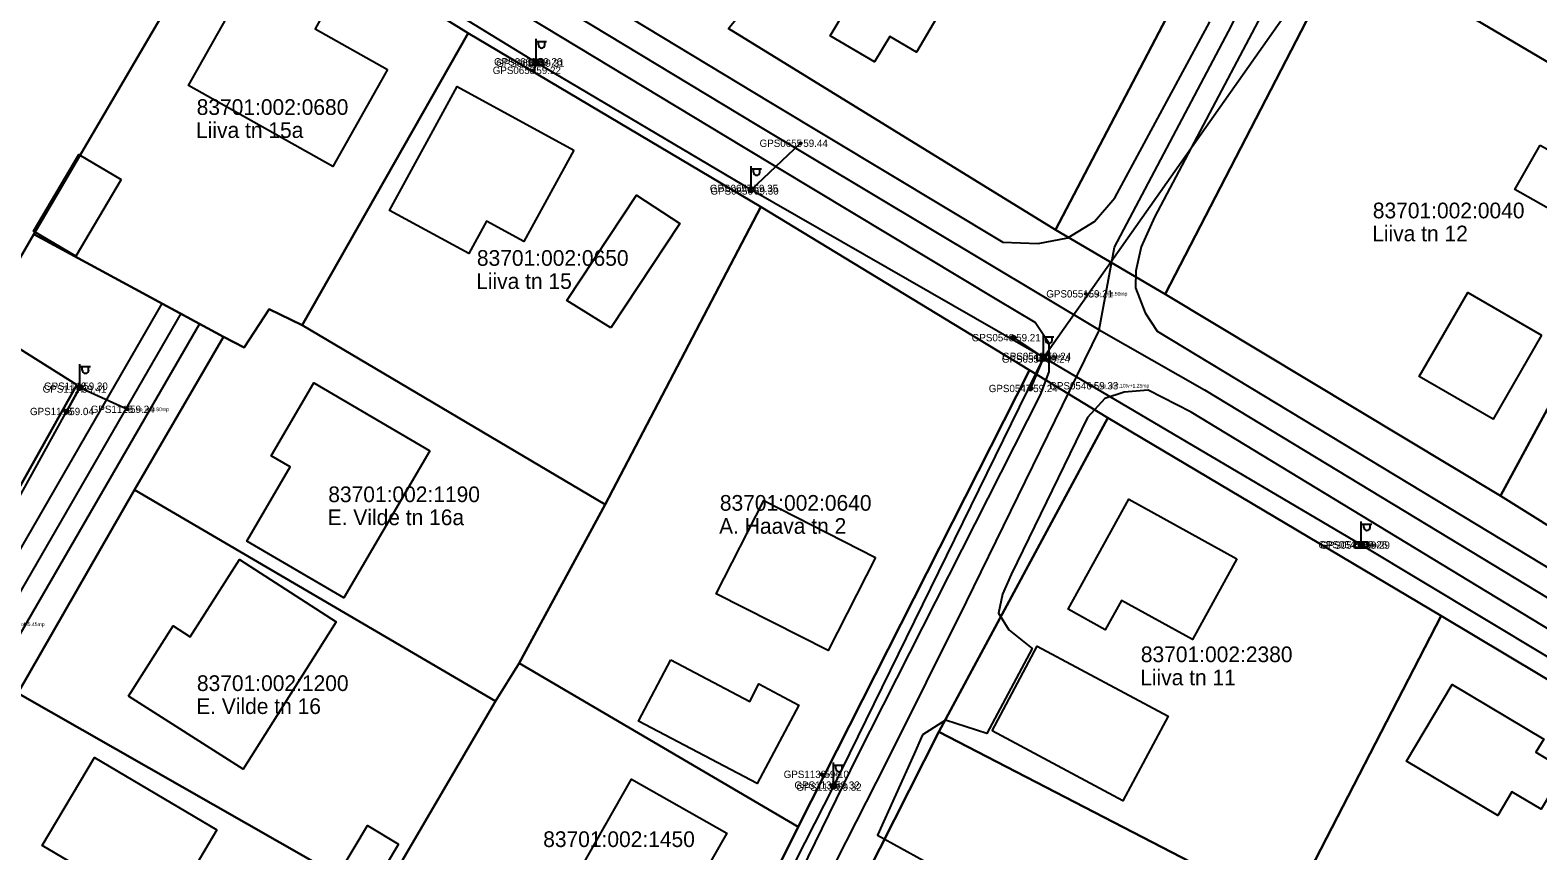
# Model space of a CAD drawing. Extents: x 580119 to 583377, y 6518915 to 6520820.
# Drawn here: x 581802.2 to 581946.3, y 6520148.1 to 6520226.6 of the extents above; entities that cross this region are included whole.
import ezdxf

# ---------------------------------------------------------------- set-up
doc = ezdxf.new("R2010")
doc.units = 0
for name, color, linetype in [('ELRAJATISMP', 7, 'Continuous'), ('Hoone Elu- või ühiskondlik hoone', 7, 'Continuous'), ('Hoone Kõrval- või tootmishoone', 7, 'Continuous'), ('L_AADRESS', 7, 'Continuous'), ('MAAMUDEL', 7, 'Continuous'), ('MOOTKORG-EH2000', 7, 'Continuous'), ('MOOTMPUNKT', 7, 'Continuous'), ('MOOTNR', 7, 'Continuous'), ('MPOHULIIN', 7, 'Continuous'), ('PIIR', 7, 'Continuous'), ('POST', 7, 'Continuous'), ('Rippe kõrgus', 7, 'Continuous'), ('Tee Liiklusala', 7, 'Continuous'), ('Tee Tänav Püsikate', 7, 'Continuous'), ('TUNNUS', 7, 'Continuous')]:
    doc.layers.add(name, color=color, linetype=linetype)

msp = doc.modelspace()

# ---------------------------------------------------------------- linework, layer by layer
at = {"layer": 'ELRAJATISMP'}
for p, q in [((581850.41, 6520223.81), (581850.41, 6520223.22)), ((581850.69, 6520223.81), (581850.69, 6520223.22)), ((581898.91, 6520195.58), (581898.91, 6520194.99)), ((581899.19, 6520195.58), (581899.19, 6520194.99)), ((581929.32, 6520177.68), (581929.32, 6520177.08)), ((581929.59, 6520177.68), (581929.59, 6520177.08))]:
    msp.add_line(p, q, dxfattribs=at)
for points in [[(581849.95, 6520223.81), (581851.15, 6520223.81), (581851.15, 6520223.22), (581849.95, 6520223.22)], [(581898.45, 6520195.58), (581899.65, 6520195.58), (581899.65, 6520194.99), (581898.45, 6520194.99)], [(581928.86, 6520177.68), (581930.05, 6520177.68), (581930.05, 6520177.08), (581928.86, 6520177.08)]]:
    msp.add_lwpolyline(points, close=True, dxfattribs=at)
at = {"layer": 'Hoone Elu- või ühiskondlik hoone'}
for points in [[(581891.94, 6520233.04), (581886.91, 6520224.51), (581884.36, 6520226.01), (581882.91, 6520223.56), (581878.68, 6520226.06), (581880.13, 6520228.52), (581877.03, 6520230.34), (581882.05, 6520238.87)], [(581836.34, 6520222.85), (581831.12, 6520213.56), (581817.32, 6520221.3), (581823.33, 6520232.01), (581830.22, 6520228.15), (581829.43, 6520226.73)], [(581854.16, 6520215.14), (581849.38, 6520206.38), (581845.8, 6520208.34), (581844.11, 6520205.25), (581836.55, 6520209.37), (581843.02, 6520221.22)], [(581946.68, 6520197.44), (581942.07, 6520189.42), (581934.99, 6520193.49), (581939.62, 6520201.52)], [(581840.4, 6520186.38), (581832.16, 6520172.31), (581822.89, 6520177.74), (581827.04, 6520184.84), (581825.21, 6520185.91), (581829.29, 6520192.88)], [(581883.01, 6520176.19), (581878.46, 6520167.27), (581867.77, 6520172.71), (581872.32, 6520181.64)], [(581917.55, 6520176.04), (581913.31, 6520168.34), (581906.53, 6520172.08), (581904.97, 6520169.27), (581901.42, 6520171.22), (581907.22, 6520181.75)], [(581811.59, 6520162.92), (581815.85, 6520169.63), (581817.48, 6520168.59), (581822.18, 6520175.99), (581831.45, 6520170.01), (581822.54, 6520155.95)], [(581948.92, 6520155.91), (581946.66, 6520152.11), (581943.85, 6520153.78), (581942.5, 6520151.5), (581933.76, 6520156.7), (581938.12, 6520164.04), (581946.9, 6520158.82), (581946.15, 6520157.56)], [(581820.03, 6520150.12), (581815.05, 6520141.71), (581803.34, 6520148.65), (581808.33, 6520157.06)], [(581852.13, 6520141.69), (581859.68, 6520154.99), (581868.78, 6520149.82), (581865.61, 6520144.24), (581867.15, 6520143.37), (581862.77, 6520135.65)]]:
    msp.add_lwpolyline(points, close=True, dxfattribs=at)
at = {"layer": 'Hoone Kõrval- või tootmishoone'}
for points in [[(581810.89, 6520212.33), (581806.56, 6520204.98), (581802.5, 6520207.37), (581806.84, 6520214.71)], [(581946.54, 6520215.6), (581950.38, 6520213.43), (581951.22, 6520214.89), (581955.32, 6520212.57), (581952.08, 6520206.86), (581944.14, 6520211.36)], [(581857.7, 6520198.14), (581853.48, 6520200.75), (581860.14, 6520210.83), (581864.28, 6520208.1)], [(581894.14, 6520159.59), (581898.47, 6520167.69), (581910.99, 6520161.01), (581906.66, 6520152.9)], [(581863.44, 6520166.4), (581870.99, 6520162.42), (581871.86, 6520164.08), (581875.67, 6520162.07), (581871.7, 6520154.55), (581860.35, 6520160.54)], [(581837.4, 6520148.76), (581834.75, 6520144.33), (581831.78, 6520146.12), (581834.43, 6520150.54)]]:
    msp.add_lwpolyline(points, close=True, dxfattribs=at)
at = {"layer": 'MOOTMPUNKT'}
for centre in [(581850.45, 6520223.58), (581850.65, 6520223.45), (581850.32, 6520222.76), (581875.84, 6520215.79), (581871.08, 6520211.47), (581871.14, 6520211.23), (581903.11, 6520201.39), (581896.19, 6520197.2), (581899, 6520195.16), (581899.1, 6520195.41), (581806.87, 6520192.29), (581807, 6520192.56), (581897.82, 6520192.34), (581903.61, 6520192.6), (581805.66, 6520190.14), (581811.47, 6520190.35), (581929.33, 6520177.4), (581929.58, 6520177.36), (581877.86, 6520155.44), (581878.89, 6520154.41), (581879.07, 6520154.22)]:
    msp.add_circle(centre, 0.1, dxfattribs=at)
at = {"layer": 'MPOHULIIN'}
for p, q in [((581899.05, 6520195.29), (581927.38, 6520235.48)), ((581850.55, 6520223.51), (581850.32, 6520222.76)), ((581871.11, 6520211.35), (581875.84, 6520215.79))]:
    msp.add_line(p, q, dxfattribs=at)
for points in [[(582074.17, 6520090.2), (582035.13, 6520113.98), (581994.07, 6520138.74), (581958.9, 6520159.67), (581929.45, 6520177.38), (581899.05, 6520195.29), (581871.11, 6520211.35), (581850.55, 6520223.51), (581830.36, 6520235.9)], [(581761.9, 6520219.5), (581748, 6520195.87), (581734.01, 6520171.83), (581727.44, 6520138.41), (581764.38, 6520118.14), (581785.49, 6520154.65), (581795.71, 6520172.16), (581806.94, 6520192.43), (581811.47, 6520190.35)], [(581899.05, 6520195.29), (581878.98, 6520154.31), (581864.42, 6520125.7), (581863.29, 6520125.92)]]:
    msp.add_lwpolyline(points, dxfattribs=at)
at = {"layer": 'PIIR'}
for points in [[(581910.68, 6520201.36), (581900.21, 6520207.51), (581917.83, 6520241.2), (581929.38, 6520263.33), (581942.22, 6520287.85), (581953.73, 6520280.26), (581951.99, 6520279.75), (581939.33, 6520256.33), (581928.04, 6520234.91)], [(581893.75, 6520257.55), (581898.1, 6520255.28), (581897.13, 6520253.13), (581917.83, 6520241.2), (581900.21, 6520207.51), (581868.94, 6520226.76)], [(581939.33, 6520256.33), (581965.72, 6520242.24), (581963.58, 6520238.14), (581954.1, 6520219.54), (581928.04, 6520234.91)], [(581796.29, 6520255.75), (581821.83, 6520240.08), (581802.53, 6520207.1), (581797.51, 6520198.44), (581771.2, 6520213.92)], [(581821.83, 6520240.08), (581844.07, 6520226.32), (581828.18, 6520198.39), (581825.04, 6520199.93), (581822.65, 6520196.25), (581820.67, 6520197.28), (581802.53, 6520207.1)], [(581928.04, 6520234.91), (581954.1, 6520219.54), (581960.82, 6520215.52), (581942.75, 6520182.07), (581910.68, 6520201.36)], [(581844.07, 6520226.32), (581872.03, 6520209.71), (581857.14, 6520181.23), (581828.18, 6520198.39)], [(581960.82, 6520215.52), (581976.76, 6520205.4), (581992.7, 6520196.04), (581974.77, 6520162.07), (581942.75, 6520182.07)], [(581771.2, 6520213.92), (581797.51, 6520198.44), (581806.64, 6520192.68), (581792.37, 6520167.22), (581755.98, 6520188.75)], [(581857.14, 6520181.23), (581872.03, 6520209.71), (581897.71, 6520194.09), (581875.62, 6520150.43), (581848.92, 6520166.07)], [(581764.96, 6520102.57), (581721.29, 6520129.05), (581728.54, 6520142.46), (581730.99, 6520136.24), (581759.52, 6520120.17), (581766.93, 6520122.61), (581782.15, 6520149.87), (581792.37, 6520167.22), (581806.64, 6520192.68), (581797.51, 6520198.44), (581802.53, 6520207.1), (581820.67, 6520197.28), (581812.15, 6520182.64), (581800.99, 6520163.2), (581790.11, 6520144.42), (581779.28, 6520127.73), (581769.84, 6520111.32), (581765.39, 6520103.31)], [(581820.67, 6520197.28), (581822.65, 6520196.25), (581825.04, 6520199.93), (581828.18, 6520198.39), (581857.14, 6520181.23), (581848.92, 6520166.07), (581846.68, 6520162.43), (581812.15, 6520182.64)], [(581818.25, 6520012.64), (581808.31, 6520018.92), (581824.83, 6520050.4), (581836.47, 6520072.82), (581851.4, 6520101.52), (581829.9, 6520114.5), (581832.4, 6520118.89), (581853.07, 6520105.93), (581865.62, 6520130.32), (581875.62, 6520150.43), (581897.71, 6520194.09), (581905.22, 6520189.53), (581889.06, 6520159.5), (581879.18, 6520139.97), (581876.38, 6520134.67), (581873.75, 6520129.28), (581870.97, 6520123.99), (581868.38, 6520118.69), (581865.54, 6520113.3), (581862.86, 6520107.92), (581858.03, 6520098.95), (581858.58, 6520096.63), (581855.23, 6520085.11)], [(581905.22, 6520189.53), (581937.09, 6520170.6), (581922.47, 6520142.22), (581889.06, 6520159.5)], [(581812.15, 6520182.64), (581846.68, 6520162.43), (581837.68, 6520147.06), (581835.4, 6520143.6), (581800.99, 6520163.2)], [(581917.89, 6520132.56), (581922.47, 6520142.22), (581937.09, 6520170.6), (581968.64, 6520151.74), (581949.67, 6520115.03), (581931.46, 6520124.92)], [(581846.68, 6520162.43), (581848.92, 6520166.07), (581875.62, 6520150.43), (581865.62, 6520130.32), (581837.68, 6520147.06)], [(581790.11, 6520144.42), (581800.99, 6520163.2), (581835.4, 6520143.6), (581823.73, 6520125.03), (581804.32, 6520136.18), (581798.27, 6520139.74)], [(581889.06, 6520159.5), (581922.47, 6520142.22), (581917.89, 6520132.56), (581931.46, 6520124.92), (581926.36, 6520115.88), (581899.93, 6520129.4), (581889.34, 6520134.93), (581879.18, 6520139.97)]]:
    msp.add_lwpolyline(points, close=True, dxfattribs=at)
for points in [[(581968.64, 6520151.74), (581937.09, 6520170.6), (581905.22, 6520189.53), (581897.71, 6520194.09), (581872.03, 6520209.71), (581844.07, 6520226.32), (581821.83, 6520240.08)], [(581868.94, 6520226.76), (581900.21, 6520207.51), (581910.68, 6520201.36), (581942.75, 6520182.07), (581974.77, 6520162.07)]]:
    msp.add_lwpolyline(points, dxfattribs=at)
at = {"layer": 'POST'}
for p, q in [((581850.55, 6520223.76), (581850.55, 6520225.76)), ((581850.55, 6520225.51), (581851.55, 6520225.51)), ((581850.78, 6520225.19), (581850.78, 6520225.51)), ((581851.39, 6520225.19), (581851.39, 6520225.51)), ((581850.55, 6520223.51), (581850.55, 6520223.51)), ((581871.11, 6520211.6), (581871.11, 6520213.6)), ((581871.11, 6520213.35), (581872.11, 6520213.35)), ((581871.33, 6520213.03), (581871.33, 6520213.35)), ((581871.95, 6520213.03), (581871.95, 6520213.35)), ((581871.11, 6520211.35), (581871.11, 6520211.35)), ((581899.05, 6520195.54), (581899.05, 6520197.54)), ((581899.05, 6520197.29), (581900.05, 6520197.29)), ((581899.28, 6520196.96), (581899.28, 6520197.29)), ((581899.89, 6520196.96), (581899.89, 6520197.29)), ((581806.94, 6520192.68), (581806.94, 6520194.68)), ((581806.94, 6520194.43), (581807.94, 6520194.43)), ((581807.16, 6520194.1), (581807.16, 6520194.43)), ((581807.77, 6520194.1), (581807.77, 6520194.43)), ((581899.05, 6520195.29), (581899.05, 6520195.29)), ((581806.94, 6520192.43), (581806.94, 6520192.43)), ((581929.45, 6520177.63), (581929.45, 6520179.63)), ((581929.45, 6520179.38), (581930.45, 6520179.38)), ((581929.68, 6520179.06), (581929.68, 6520179.38)), ((581930.29, 6520179.06), (581930.29, 6520179.38)), ((581929.45, 6520177.38), (581929.45, 6520177.38)), ((581878.98, 6520154.56), (581878.98, 6520156.56)), ((581878.98, 6520156.31), (581879.98, 6520156.31)), ((581879.2, 6520155.99), (581879.2, 6520156.31)), ((581879.82, 6520155.99), (581879.82, 6520156.31)), ((581878.98, 6520154.31), (581878.98, 6520154.31))]:
    msp.add_line(p, q, dxfattribs=at)
for points in [[(581896.19, 6520197.2), (581899.05, 6520195.29)], [(581899.05, 6520195.29), (581897.82, 6520192.34)], [(581806.94, 6520192.43), (581805.66, 6520190.14)]]:
    msp.add_lwpolyline(points, dxfattribs=at)
for centre, radius in [((581850.55, 6520223.51), 0.25), ((581871.11, 6520211.35), 0.25), ((581896.19, 6520197.2), 0.2), ((581899.05, 6520195.29), 0.25), ((581806.94, 6520192.43), 0.25), ((581897.82, 6520192.34), 0.2), ((581805.66, 6520190.14), 0.2), ((581929.45, 6520177.38), 0.25), ((581878.98, 6520154.31), 0.25)]:
    msp.add_circle(centre, radius, dxfattribs=at)
for centre in [(581851.08, 6520225.19), (581871.64, 6520213.03), (581899.58, 6520196.96), (581807.47, 6520194.1), (581929.99, 6520179.06), (581879.51, 6520155.99)]:
    msp.add_arc(centre, 0.306, 180, 0, dxfattribs=at)
at = {"layer": 'Tee Liiklusala'}
for points in [[(581948.5, 6520280.84), (581946.04, 6520279.06), (581930.52, 6520249.11), (581924.23, 6520236.3), (581909.68, 6520208.73), (581908.39, 6520205.89), (581907.88, 6520203.6), (581907.85, 6520201.97), (581908.78, 6520199.57), (581909.94, 6520197.81), (581951.81, 6520172.47)], [(581791.12, 6520254.22), (581773.63, 6520225.91), (581735.3, 6520162.16), (581723.93, 6520142.16), (581723.3, 6520139.96), (581724.17, 6520137.95), (581725.95, 6520135.82), (581760.56, 6520117.9), (581762.96, 6520117.57), (581764.66, 6520117.64), (581767.58, 6520119), (581787.09, 6520152.49), (581814.8, 6520200.48), (581816.61, 6520199.5), (581818.38, 6520198.53), (581788.51, 6520146.96), (581766.84, 6520109), (581723.69, 6520132.04), (581721.59, 6520132.47), (581719.38, 6520131.9), (581717.46, 6520130.63), (581696.84, 6520096.06), (581693.74, 6520090.36)], [(581822.23, 6520250.37), (581872.96, 6520219.7), (581895.19, 6520206.32), (581898.56, 6520206.21), (581901.38, 6520206.75), (581903.94, 6520208.3), (581905.87, 6520210.56), (581914.97, 6520227.4)], [(581859.04, 6520111.64), (581881.29, 6520157.17), (581898.78, 6520191.73), (581899.61, 6520193.92), (581899.59, 6520196.64), (581898.27, 6520198.65), (581894.62, 6520200.82), (581870.38, 6520215.42), (581819.67, 6520246.07)], [(581949.23, 6520168.19), (581913.19, 6520190.06), (581909.08, 6520192.18), (581906.79, 6520192), (581904.93, 6520191.39), (581903.27, 6520189.57), (581895.98, 6520174.56), (581895.14, 6520172.67), (581894.75, 6520170.86), (581895.76, 6520169.26), (581897.98, 6520167.46), (581893.65, 6520159.36), (581889.7, 6520160.62), (581887.5, 6520159.21), (581886.71, 6520157.39), (581883.18, 6520149.64), (581887.58, 6520147.2)]]:
    msp.add_lwpolyline(points, dxfattribs=at)
at = {"layer": 'Tee Tänav Püsikate'}
for points in [[(581904.38, 6520197.95), (581905.85, 6520205.86), (581916.75, 6520226.48), (581928.74, 6520250.02), (581944.37, 6520280.16), (581950.77, 6520287.95)], [(581794.4, 6520263.72), (581820.95, 6520248.22), (581871.67, 6520217.56), (581904.38, 6520197.95)], [(581718.97, 6520136.73), (581766.53, 6520112.73), (581816.61, 6520199.5)], [(581904.38, 6520197.95), (581891.67, 6520171.94), (581884.02, 6520156.58), (581876.34, 6520141.46), (581857.05, 6520101.08)], [(581904.38, 6520197.95), (581914.45, 6520192.22), (581950.52, 6520170.33), (581994.47, 6520143.85), (582121.99, 6520066.88), (582130.06, 6520062.7)]]:
    msp.add_lwpolyline(points, dxfattribs=at)

# ---------------------------------------------------------------- texts
at = {"layer": 'L_AADRESS'}
for s, p in [('Liiva tn 15a', (581818.04, 6520216.3)), ('Liiva tn 12', (581930.49, 6520206.41)), ('Liiva tn 15', (581844.82, 6520201.86)), ('E. Vilde tn 16a', (581830.62, 6520179.27)), ('A. Haava tn 2', (581868.05, 6520178.44)), ('Liiva tn 11', (581908.31, 6520163.96)), ('E. Vilde tn 16', (581818.05, 6520161.21))]:
    msp.add_text(s, height=1.5, dxfattribs=at).set_placement(p)
at = {"layer": 'MAAMUDEL'}
for s, p in [(' kilp', (581850.45, 6520223.4)), (' kilp', (581850.65, 6520223.28)), (' kaabel', (581899, 6520194.99)), (' kaabel', (581899.1, 6520195.24)), (' kaabel', (581929.33, 6520177.23)), (' kaabel', (581929.58, 6520177.18)), (' mp_ohl', (581877.86, 6520155.26))]:
    msp.add_text(s, height=0.35, dxfattribs=at).set_placement(p)
at = {"layer": 'MOOTKORG-EH2000'}
for s, p in [(' 59.22', (581850.32, 6520222.41)), (' 59.26', (581850.45, 6520223.23)), (' 59.31', (581850.65, 6520223.1)), (' 59.44', (581875.84, 6520215.44)), (' 59.35', (581871.08, 6520211.12)), (' 59.30', (581871.14, 6520210.88)), (' 59.21', (581903.11, 6520201.04)), (' 59.21', (581896.19, 6520196.85)), (' 59.24', (581899.1, 6520195.06)), (' 59.24', (581899, 6520194.81)), (' 59.30', (581807, 6520192.21)), (' 59.33', (581903.61, 6520192.25)), (' 59.41', (581806.87, 6520191.94)), (' 59.24', (581897.82, 6520191.99)), (' 59.04', (581805.66, 6520189.79)), (' 59.24', (581811.47, 6520190)), (' 59.26', (581929.33, 6520177.05)), (' 59.29', (581929.58, 6520177.01)), (' 59.10', (581877.86, 6520155.09)), (' 59.32', (581878.89, 6520154.06)), (' 59.32', (581879.07, 6520153.87))]:
    msp.add_text(s, height=0.7, dxfattribs=at).set_placement(p)
at = {"layer": 'MOOTNR'}
for s, p in [('GPS0658 ', (581846.4, 6520222.41)), ('GPS0660 ', (581846.53, 6520223.23)), ('GPS0659 ', (581846.73, 6520223.1)), ('GPS0655 ', (581871.92, 6520215.44)), ('GPS0657 ', (581867.16, 6520211.12)), ('GPS0656 ', (581867.22, 6520210.88)), ('GPS0551 ', (581899.33, 6520201.04)), ('GPS0548 ', (581892.2, 6520196.85)), ('GPS0549 ', (581895.11, 6520195.06)), ('GPS0550 ', (581895.08, 6520194.81)), ('GPS1118 ', (581803.5, 6520192.21)), ('GPS0546 ', (581899.62, 6520192.25)), ('GPS1117 ', (581803.37, 6520191.94)), ('GPS0547 ', (581893.83, 6520191.99)), ('GPS1116 ', (581802.16, 6520189.79)), ('GPS1115 ', (581807.97, 6520190)), ('GPS0545 ', (581925.34, 6520177.05)), ('GPS0544 ', (581925.52, 6520177.01)), ('GPS1138 ', (581874.22, 6520155.09)), ('GPS1137 ', (581875.25, 6520154.06)), ('GPS1136 ', (581875.43, 6520153.87))]:
    msp.add_text(s, height=0.7, dxfattribs=at).set_placement(p)
at = {"layer": 'Rippe kõrgus'}
for s, p in [(' el_mp_ohl8.50mp', (581903.11, 6520201.22)), (' el_mp_ohl7.10tv+1.25mp', (581903.61, 6520192.43)), (' el_mp_ohl4.80mp', (581811.47, 6520190.17)), (' el_mp_ohl5.45mp', (581799.58, 6520169.62))]:
    msp.add_text(s, height=0.35, dxfattribs=at).set_placement(p)
at = {"layer": 'TUNNUS'}
for s, p in [('83701:002:0680', (581818.1, 6520218.5)), ('83701:002:0040', (581930.55, 6520208.61)), ('83701:002:0650', (581844.89, 6520204.07)), ('83701:002:1190', (581830.68, 6520181.47)), ('83701:002:0640', (581868.12, 6520180.65)), ('83701:002:2380', (581908.37, 6520166.17)), ('83701:002:1200', (581818.12, 6520163.41)), ('83701:002:1450', (581851.23, 6520148.49))]:
    msp.add_text(s, height=1.5, dxfattribs=at).set_placement(p)

doc.saveas('drawing.dxf')
